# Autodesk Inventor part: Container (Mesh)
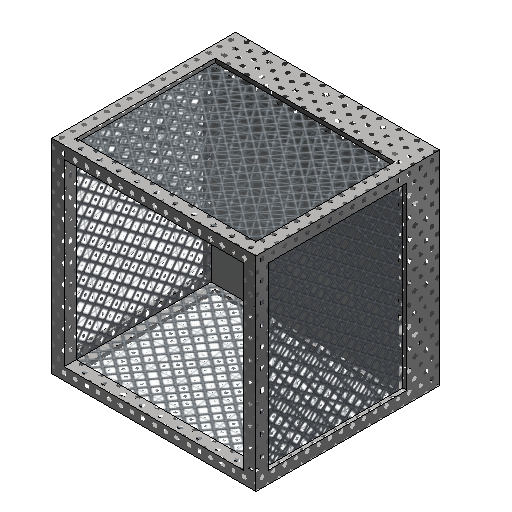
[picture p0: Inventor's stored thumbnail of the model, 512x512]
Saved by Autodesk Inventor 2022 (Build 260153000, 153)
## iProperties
RuleStatus: InUse
Created: 2009-09
Part Number: Container (Mesh)
Document SubType Name: Modeling
Designer: Autodesk, Inc.
Density: 1 g/cm^3
Material: 一般
Appearance: ステンレス - サテン 粗い 網状
Key Parameters: Length=815.000 mm;Width=815.000 mm;Height=815.000 mm;
Author: Autodesk, Inc.
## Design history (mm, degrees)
sketch "Sketch1"
  geometry: L1 (0, 0)-(-815, 0); L2 (-815, 0)-(-815, 815); L3 (-815, 815)-(0, 815); L4 (0, 815)-(0, 0)
  constraints: 8 end point, 2 parallel, 1 horizontal, 1 perpendicular
  dimensions: "d0" = 815 distance of L1.end L2.end (derived); "d1" = 815 distance of L1.start L1.end (derived)
extrude "Extrusion1" new body sketch "Sketch1" distance "d2" = 652 (= BoxHeight); taper "d3" = 0 deg
shell "Shell1" dims "d4" = 48.9 (= BoxThickness)
sketch "Sketch6"
  geometry: L1 (0, 0)-(717.2, 0) reference; L2 (717.2, 0)-(717.2, -554.2) reference; L3 (717.2, -554.2)-(0, -554.2) reference; L4 (0, -554.2)-(0, 0) reference; L5 (717.2, -554.2)-(0, -554.2); L6 (0, -554.2)-(0, 0); L7 (0, 0)-(717.2, 0); L8 (717.2, 0)-(717.2, -554.2); 3 further points
  constraints: 8 end point, 2 parallel, 1 horizontal, 1 perpendicular
  dimensions: "d40" = 717.2 distance of L2.end L5.end (derived); "d41" = 603.1 distance of point (717.2, -603.1) point (717.2, 0) (derived)
extrude "Extrusion4" cut sketch "Sketch6" distance "d42" = 16.3 (= FaceFilletThickness); taper "d43" = 0 deg
workplane "Work Plane2"
mirror "Mirror2"
sketch "Sketch7"
  geometry: L1 (-48.9, -16.3)-(-603.1, -16.3) reference; L2 (-48.9, 733.5)-(-603.1, 733.5) reference; L3 (-603.1, 0)-(-603.1, 717.2) reference; L4 (-603.1, 717.2)-(-48.9, 717.2) reference; L5 (-48.9, 717.2)-(-48.9, 0) reference; L6 (-48.9, 0)-(-603.1, 0) reference; L7 (-48.9, 733.5)-(-603.1, 733.5); L8 (-603.1, 733.5)-(-603.1, -16.3); L9 (-603.1, -16.3)-(-48.9, -16.3); L10 (-48.9, -16.3)-(-48.9, 733.5); 1 further point
  constraints: 8 end point, 2 parallel, 1 horizontal, 1 perpendicular
  dimensions: "d44" = 749.8 distance of L9.end L2.start (derived); "d45" = 554.2 distance of L3.end L4.end (derived)
extrude "Extrusion5" cut sketch "Sketch7" distance "d46" = 16.3 (= FaceFilletThickness); taper "d47" = 0 deg
workplane "Work Plane4"
mirror "Mirror4"
sketch "Sketch8"
  geometry: L1 (0, 0)-(0, 815) reference; L2 (815, 0)-(0, 0) reference; L3 (815, 815)-(815, 0) reference; L4 (0, 815)-(815, 815) reference; L5 (0, 0)-(0, 815) reference; L6 (815, 0)-(0, 0) reference; L7 (815, 815)-(815, 0) reference; L8 (0, 815)-(815, 815) reference; L9 (0, 0)-(815, 0); L10 (815, 0)-(815, 815); L11 (815, 815)-(0, 815); L12 (0, 815)-(0, 0)
  constraints: 8 end point, 2 parallel, 1 horizontal, 1 perpendicular
  dimensions: "d48" = 815 distance of L11.end L5.start (derived); "d49" = 815 distance of L2.start L1.start (derived)
extrude "Extrusion6" join sketch "Sketch8" distance "d50" = 81.5 (= LegHeight); taper "d51" = 0 deg
sketch "Sketch9"
  geometry: L1 (0, 0)-(81.5, 81.5); L2 (81.5, 81.5)-(244.5, 81.5); L3 (244.5, 81.5)-(244.5, 244.5); L4 (244.5, 244.5)-(81.5, 244.5); L5 (81.5, 244.5)-(81.5, 81.5)
  constraints: 10 end point, 2 parallel, 1 horizontal, 1 perpendicular
  dimensions: "d52" = 81.5 horizontal distance of L1.start L1.end (= LegPosition); "d53" = 81.5 horizontal distance of L1.start L1.end (= LegPosition); "d54" = 163 distance of L2.end L3.end (= LegLength); "d55" = 163 distance of L3.end L4.end (= LegLength)
extrude "Extrusion7" join sketch "Sketch9" distance "d56" = 81.5 (= LegHeight); taper "d57" = 0 deg
workpoint "Work Point1"
  workaxis "Work Axis1"
node "Landing Surface"
node "Insertion Point1"
body "Solid1"
sketch "Sketch4"
  geometry: L1 (0, -652)-(815, -652) reference; L2 (815, 0)-(815, -652) reference; L3 (815, 0)-(0, 0) reference; L4 (0, 0)-(0, -652) reference; L5 (0, -326)-(48.9, -326); L6 (48.9, -326)-(48.9, -48.9); L7 (48.9, -48.9)-(766.1, -48.9); L8 (766.1, -48.9)-(766.1, -603.1); L9 (766.1, -603.1)-(48.9, -603.1); L10 (48.9, -603.1)-(48.9, -326); 2 further points
  constraints: 12 end point, 3 parallel, 2 collinear, 2 perpendicular, 1 midpoint
  dimensions: "d26" = 717.2 distance of L6.end L7.end (= FaceFilletWidth); "d27" = 48.9 distance of L5.start L5.end (= BoxThickness); "d28" = 277.1 distance of L5.end L6.end (= FaceFilletHeight)
extrude "Extrusion2" cut sketch "Sketch4" distance "d29" = 16.3 (= FaceFilletThickness); taper "d30" = 0 deg
mirror "Mirror1"
sketch "Sketch5"
  geometry: L1 (652, 0)-(652, 815) reference; L2 (0, 815)-(652, 815) reference; L3 (0, 815)-(0, 0) reference; L4 (0, 0)-(652, 0) reference; L5 (326, 0)-(326, 48.9); L6 (326, 48.9)-(48.9, 48.9); L7 (48.9, 48.9)-(48.9, 766.1); L8 (48.9, 766.1)-(603.1, 766.1); L9 (603.1, 766.1)-(603.1, 48.9); L10 (603.1, 48.9)-(326, 48.9); 2 further points
  constraints: 12 end point, 3 parallel, 2 collinear, 2 perpendicular, 1 midpoint
  dimensions: "d33" = 48.9 distance of L5.start L5.end (= BoxThickness); "d34" = 717.2 distance of L6.end L7.end (= FaceFilletLength); "d35" = 277.1 distance of L5.end L6.end (= FaceFilletHeight)
extrude "Extrusion3" cut sketch "Sketch5" distance "d36" = 16.3 (= FaceFilletThickness); taper "d37" = 0 deg
mirror "Mirror3"
pattern_linear "Rectangular Pattern1" dims "d60" = 489 (= ArrayWidth), "d63" = 489 (= ArrayLength)
node "Projected Loop2"
node "Projected Loop3"
node "Projected Loop4"
node "Projected Loop5"
node "Projected Loop6"
workplane "Work Plane5"
workplane "Work Plane6"
other parameters: "WallThicknessIn" = 1 [user parameter], "WallThicknessOut" = 1 [user parameter], "d32" = 407.5 (= WidthPlane), "d39" = -407.5 (= LengthPlane), "BoxHeight" = 652 [user parameter; used in 2 equation terms], "BoxThickness" = 48.9 [user parameter; used in 4 equation terms], "LegHeight" = 81.5 [user parameter; used in 3 equation terms], "LegPosition" = 81.5 [user parameter; used in 3 equation terms], "LegLength" = 163 [user parameter; used in 3 equation terms], "FaceFilletThickness" = 16.3 [user parameter; used in 5 equation terms], "LengthPlane" = -407.5 [user parameter; used in 2 equation terms], "WidthPlane" = 407.5 [user parameter; used in 2 equation terms], "FaceFilletHeight" = 277.1 [user parameter; used in 3 equation terms], "ArrayLength" = 489 [user parameter; used in 2 equation terms], "FaceFilletLength" = 717.2 [user parameter; used in 2 equation terms], "FaceFilletWidth" = 717.2 [user parameter; used in 2 equation terms], "ArrayWidth" = 489 [user parameter; used in 2 equation terms]
